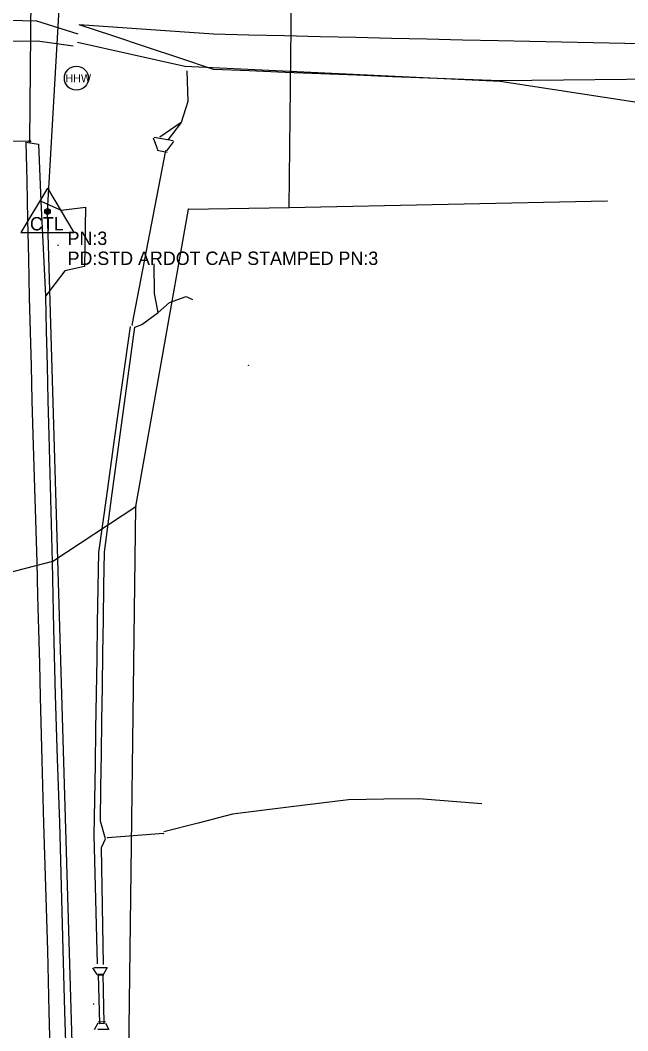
# Model space of a CAD drawing. Extents: x 1930288 to 1941089, y 588389 to 611475.
# Drawn here: x 1930884 to 1931111.5, y 597803.8 to 598182.1 of the extents above; entities that cross this region are included whole.
import ezdxf

# ---------------------------------------------------------------- set-up
doc = ezdxf.new("R2010")
doc.units = 0
for name, color, linetype in [('S_BASELINE', 7, 'Continuous'), ('S_BRIDGE', 7, 'Continuous'), ('S_CROSS_DRAIN', 7, 'Continuous'), ('S_DITCHLINE', 7, 'Continuous'), ('S_DRG_PT_SYM', 7, 'Continuous'), ('S_DRIVEWAY', 7, 'Continuous'), ('S_EDGE_CONCRETE', 7, 'Continuous'), ('S_EDGE_PAVEMENT', 7, 'Continuous'), ('S_HEADWALL', 7, 'Continuous'), ('S_HIST_HIGH_WATER', 7, 'Continuous'), ('S_MSC_PT_SYM', 7, 'Continuous'), ('S_PRIMARY_CTL', 7, 'Continuous'), ('S_PRIMARY_CTL_ANNOT', 7, 'Continuous'), ('S_SANITARY_SEWER', 7, 'Continuous'), ('S_SHOULDER', 7, 'Continuous'), ('S_SIDE_DRAIN', 7, 'Continuous'), ('S_STR_PT_SYM', 7, 'Continuous'), ('S_STREAM', 7, 'Continuous'), ('S_UTL_PT_SYM', 7, 'Continuous'), ('S_WALL', 7, 'Continuous')]:
    doc.layers.add(name, color=color, linetype=linetype)

msp = doc.modelspace()

# ---------------------------------------------------------------- linework, layer by layer
at = {"layer": 'S_BASELINE'}
for p, q in [((1930894.27, 598110.49), (1930946.09, 599020.44)), ((1930922.05, 597172.86), (1930894.27, 598110.49))]:
    msp.add_line(p, q, dxfattribs=at)
at = {"layer": 'S_BRIDGE'}
for p, q in [((1930887.7, 598136.81), (1930888.36, 598226.99)), ((1930860.05, 598137.01), (1930887.7, 598136.81))]:
    msp.add_line(p, q, dxfattribs=at)
at = {"layer": 'S_CROSS_DRAIN'}
for p, q in [((1930915.08, 597824.99), (1930913.16, 597824.9)), ((1930913.16, 597824.9), (1930913.69, 597806.45)), ((1930915.48, 597806.65), (1930915.08, 597824.99)), ((1930913.69, 597806.45), (1930915.48, 597806.65))]:
    msp.add_line(p, q, dxfattribs=at)
at = {"layer": 'S_DITCHLINE'}
for points in [[(1930905.69, 598176.9), (1930890.32, 598181.8), (1930873.87, 598182.1), (1930857.41, 598182.4)], [(1931134.66, 598160.16), (1931111.01, 598159.9), (1931087.35, 598159.64), (1931063.69, 598159.38), (1931050.28, 598159.92), (1931036.87, 598160.45), (1931023.45, 598160.98), (1931010.04, 598161.52), (1930996.63, 598162.05), (1930983.21, 598162.58), (1930969.8, 598163.12), (1930956.39, 598163.65), (1930943.82, 598167.85), (1930931.26, 598172.05), (1930918.7, 598176.25), (1930906.14, 598180.45)], [(1931134.09, 598172.94), (1931110.37, 598173.41), (1931086.65, 598173.88), (1931062.93, 598174.35), (1931049.6, 598174.67), (1931036.28, 598174.99), (1931022.96, 598175.31), (1931009.63, 598175.63), (1930996.31, 598175.95), (1930982.98, 598176.27), (1930969.66, 598176.58), (1930956.34, 598176.9), (1930943.79, 598177.79), (1930931.24, 598178.67), (1930918.69, 598179.56), (1930906.14, 598180.45)], [(1930946.46, 598163.13), (1930946.75, 598151.72), (1930944.27, 598143.85), (1930936.29, 598138.31)], [(1930944.27, 598143.85), (1930939.45, 598137.46)], [(1930915.22, 597828.56), (1930914.87, 597850.48), (1930914.51, 597872.4), (1930915.91, 597875.69), (1930914.06, 597882.24), (1930914.25, 597894.82), (1930914.43, 597907.41), (1930914.62, 597919.99), (1930914.8, 597932.58), (1930914.99, 597945.17), (1930915.18, 597957.75), (1930915.36, 597970.34), (1930915.55, 597982.92), (1930918.38, 598003.99), (1930921.22, 598025.05), (1930924.05, 598046.11), (1930926.89, 598067.17), (1930929.51, 598068.22), (1930935.64, 598072.72), (1930934.26, 598079.76), (1930934.12, 598090.96)], [(1930935.64, 598072.72), (1930939.88, 598076.44), (1930946.19, 598078.67), (1930948.52, 598077.53)], [(1930913.02, 597828.8), (1930912.39, 597852.92), (1930911.76, 597877.04), (1930911.97, 597890.26), (1930912.18, 597903.49), (1930912.39, 597916.71), (1930912.6, 597929.94), (1930912.82, 597943.16), (1930913.03, 597956.39), (1930913.24, 597969.61), (1930913.45, 597982.84), (1930916.41, 598004), (1930919.38, 598025.16), (1930922.34, 598046.32), (1930925.31, 598067.48)], [(1931056.88, 597888.8), (1931033.31, 597890.66), (1931020.1, 597890.46), (1931006.89, 597890.27), (1930985.47, 597887.61), (1930963.53, 597884.9), (1930950.67, 597881.55), (1930937.8, 597878.2)]]:
    msp.add_lwpolyline(points, dxfattribs=at)
at = {"layer": 'S_DRG_PT_SYM'}
for points in [[(1930938.59, 598133.29), (1930938.59, 598133.34), (1930938.59, 598133.29), (1930938.54, 598133.29), (1930938.59, 598133.29), (1930938.59, 598133.24), (1930938.59, 598133.29), (1930938.64, 598133.29)], [(1930925.96, 598067.95), (1930925.96, 598068), (1930925.96, 598067.95), (1930925.91, 598067.95), (1930925.96, 598067.95), (1930925.96, 598067.9), (1930925.96, 598067.95), (1930926.01, 598067.95)], [(1930916.75, 597876.04), (1930916.75, 597876.09), (1930916.75, 597876.04), (1930916.7, 597876.04), (1930916.75, 597876.04), (1930916.75, 597875.99), (1930916.75, 597876.04), (1930916.8, 597876.04)], [(1930937.73, 597877.68), (1930937.73, 597877.73), (1930937.73, 597877.68), (1930937.68, 597877.68), (1930937.73, 597877.68), (1930937.73, 597877.63), (1930937.73, 597877.68), (1930937.78, 597877.68)], [(1930913.16, 597824.9), (1930913.16, 597824.95), (1930913.16, 597824.9), (1930913.11, 597824.9), (1930913.16, 597824.9), (1930913.16, 597824.85), (1930913.16, 597824.9), (1930913.21, 597824.9)], [(1930915.08, 597824.99), (1930915.08, 597825.04), (1930915.08, 597824.99), (1930915.03, 597824.99), (1930915.08, 597824.99), (1930915.08, 597824.94), (1930915.08, 597824.99), (1930915.13, 597824.99)], [(1930913.69, 597806.45), (1930913.69, 597806.5), (1930913.69, 597806.45), (1930913.64, 597806.45), (1930913.69, 597806.45), (1930913.69, 597806.4), (1930913.69, 597806.45), (1930913.74, 597806.45)], [(1930915.48, 597806.65), (1930915.48, 597806.7), (1930915.48, 597806.65), (1930915.43, 597806.65), (1930915.48, 597806.65), (1930915.48, 597806.6), (1930915.48, 597806.65), (1930915.53, 597806.65)]]:
    msp.add_lwpolyline(points, dxfattribs=at)
at = {"layer": 'S_DRIVEWAY'}
msp.add_lwpolyline([(1930891.77, 598114.39), (1930899.31, 598110.95), (1930908.51, 598112.07), (1930908.08, 598089.95), (1930900.79, 598088.32), (1930893.51, 598078.86)], dxfattribs=at)
at = {"layer": 'S_EDGE_CONCRETE'}
for points in [[(1930941.29, 598136.92), (1930934.21, 598138.16)], [(1930911.68, 597827.45), (1930916.28, 597827.51)], [(1930916.82, 597804.31), (1930913.05, 597804.29)]]:
    msp.add_lwpolyline(points, dxfattribs=at)
at = {"layer": 'S_EDGE_PAVEMENT'}
msp.add_lwpolyline([(1930886.18, 598136.44), (1930886.5, 598121.9), (1930886.81, 598107.36), (1930887.13, 598092.81), (1930887.44, 598078.27), (1930887.78, 598065.43), (1930888.11, 598052.59), (1930888.44, 598039.75), (1930888.78, 598026.91), (1930889.5, 598003.04), (1930890.23, 597979.17), (1930890.56, 597966.56), (1930890.9, 597953.94), (1930891.23, 597941.32), (1930891.57, 597928.7), (1930892.18, 597905.05), (1930892.79, 597881.4), (1930893.5, 597857.62), (1930894.2, 597833.84), (1930894.81, 597810.89), (1930895.42, 597787.94)], dxfattribs=at)
at = {"layer": 'S_HEADWALL'}
for points in [[(1930935.25, 598133.48), (1930939.05, 598132.75)], [(1930915.38, 597824.59), (1930913, 597824.51)], [(1930913.17, 597807.18), (1930916, 597807.26)]]:
    msp.add_lwpolyline(points, dxfattribs=at)
at = {"layer": 'S_HIST_HIGH_WATER'}
msp.add_circle((1930905.06, 598160.41), 4.5, dxfattribs=at)
at = {"layer": 'S_MSC_PT_SYM'}
for points in [[(1930898.23, 598097.85), (1930898.23, 598097.9), (1930898.23, 598097.85), (1930898.18, 598097.85), (1930898.23, 598097.85), (1930898.23, 598097.8), (1930898.23, 598097.85), (1930898.28, 598097.85)], [(1930969.55, 598052.91), (1930969.55, 598052.96), (1930969.55, 598052.91), (1930969.5, 598052.91), (1930969.55, 598052.91), (1930969.55, 598052.86), (1930969.55, 598052.91), (1930969.6, 598052.91)], [(1930911.56, 597813.77), (1930911.56, 597813.82), (1930911.56, 597813.77), (1930911.51, 597813.77), (1930911.56, 597813.77), (1930911.56, 597813.72), (1930911.56, 597813.77), (1930911.61, 597813.77)]]:
    msp.add_lwpolyline(points, dxfattribs=at)
at = {"layer": 'S_PRIMARY_CTL'}
for p, q in [((1930894.27, 598119.19), (1930884.23, 598102.68)), ((1930894.27, 598119.19), (1930904.09, 598102.68)), ((1930884.23, 598102.68), (1930904.09, 598102.68))]:
    msp.add_line(p, q, dxfattribs=at)
for radius in [1.04, 0.609, 0.344]:
    msp.add_circle((1930894.27, 598110.49), radius, dxfattribs=at)
at = {"layer": 'S_SANITARY_SEWER'}
for p, q in [((1930984.75, 598112), (1930985.88, 598222.31)), ((1930984.75, 598112), (1931103.79, 598114.5)), ((1930927.31, 598000.04), (1930946.98, 598111.43)), ((1930946.98, 598111.43), (1930984.75, 598112)), ((1930896.27, 597979.53), (1930927.31, 598000.04)), ((1930923.55, 597706.51), (1930927.31, 598000.04)), ((1930837.54, 597964.65), (1930896.27, 597979.53))]:
    msp.add_line(p, q, dxfattribs=at)
at = {"layer": 'S_SHOULDER'}
msp.add_lwpolyline([(1930886.18, 598136.44), (1930890.92, 598135.72), (1930891.77, 598114.39), (1930892.64, 598096.62), (1930893.51, 598078.86), (1930893.81, 598065.81), (1930894.12, 598052.77), (1930894.43, 598039.73), (1930894.73, 598026.69), (1930895.36, 598002.96), (1930895.98, 597979.24), (1930896.54, 597954.32), (1930897.11, 597929.39), (1930897.92, 597905.55), (1930898.74, 597881.7), (1930899.35, 597857.88), (1930899.96, 597834.06), (1930900.65, 597810.97), (1930901.33, 597787.88)], dxfattribs=at)
at = {"layer": 'S_SIDE_DRAIN'}
for p, q in [((1930925.96, 598067.95), (1930938.59, 598133.29)), ((1930937.73, 597877.68), (1930916.75, 597876.04))]:
    msp.add_line(p, q, dxfattribs=at)
at = {"layer": 'S_STR_PT_SYM'}
msp.add_lwpolyline([(1930887.7, 598136.81), (1930887.7, 598137.31), (1930887.7, 598136.81), (1930887.2, 598136.81), (1930887.7, 598136.81), (1930887.7, 598136.31), (1930887.7, 598136.81), (1930888.2, 598136.81)], dxfattribs=at)
at = {"layer": 'S_STREAM'}
for points in [[(1930903.84, 598172.42), (1930890.52, 598174.33), (1930874.09, 598174.21), (1930857.65, 598174.09), (1930841.52, 598174.78), (1930825.38, 598175.47), (1930810.24, 598178.46), (1930795.11, 598181.46), (1930779.97, 598184.46)], [(1931454.95, 598149.53), (1931355.72, 598149.5), (1931273.21, 598145.7), (1931162.17, 598144.02), (1931063.69, 598159.12), (1930945.68, 598164.75), (1930905.43, 598173.73)]]:
    msp.add_lwpolyline(points, dxfattribs=at)
at = {"layer": 'S_UTL_PT_SYM'}
for points in [[(1931103.79, 598114.5), (1931103.79, 598114.55), (1931103.79, 598114.5), (1931103.74, 598114.5), (1931103.79, 598114.5), (1931103.79, 598114.45), (1931103.79, 598114.5), (1931103.84, 598114.5)], [(1930946.98, 598111.43), (1930946.98, 598111.48), (1930946.98, 598111.43), (1930946.93, 598111.43), (1930946.98, 598111.43), (1930946.98, 598111.38), (1930946.98, 598111.43), (1930947.03, 598111.43)], [(1930984.75, 598112), (1930984.75, 598112.05), (1930984.75, 598112), (1930984.7, 598112), (1930984.75, 598112), (1930984.75, 598111.95), (1930984.75, 598112), (1930984.8, 598112)], [(1930984.75, 598112), (1930984.75, 598112.05), (1930984.75, 598112), (1930984.7, 598112), (1930984.75, 598112), (1930984.75, 598111.95), (1930984.75, 598112), (1930984.8, 598112)], [(1930927.31, 598000.04), (1930927.31, 598000.09), (1930927.31, 598000.04), (1930927.26, 598000.04), (1930927.31, 598000.04), (1930927.31, 597999.99), (1930927.31, 598000.04), (1930927.36, 598000.04)], [(1930927.31, 598000.04), (1930927.31, 598000.09), (1930927.31, 598000.04), (1930927.26, 598000.04), (1930927.31, 598000.04), (1930927.31, 597999.99), (1930927.31, 598000.04), (1930927.36, 598000.04)], [(1930896.27, 597979.53), (1930896.27, 597979.58), (1930896.27, 597979.53), (1930896.22, 597979.53), (1930896.27, 597979.53), (1930896.27, 597979.48), (1930896.27, 597979.53), (1930896.32, 597979.53)]]:
    msp.add_lwpolyline(points, dxfattribs=at)
at = {"layer": 'S_WALL'}
for points in [[(1930933.8, 598138.05), (1930935.48, 598133.74)], [(1930938.95, 598133.23), (1930941.5, 598136.69)], [(1930912.81, 597824.82), (1930911.25, 597827.32)], [(1930916.65, 597827.42), (1930915.24, 597824.95)], [(1930911.89, 597804.29), (1930913.24, 597806.71)], [(1930916, 597806.67), (1930917.24, 597804.23)]]:
    msp.add_lwpolyline(points, dxfattribs=at)

# ---------------------------------------------------------------- texts
at = {"layer": 'S_HIST_HIGH_WATER'}
msp.add_text('HHW', height=3, rotation=360, dxfattribs=at).set_placement((1930900.98, 598158.91))
at = {"layer": 'S_PRIMARY_CTL'}
msp.add_text('CTL', height=5, rotation=360, dxfattribs=at).set_placement((1930887.68, 598103.42))
at = {"layer": 'S_PRIMARY_CTL_ANNOT'}
for s, p in [('PN:3', (1930901.77, 598097.99)), ('PD:STD ARDOT CAP STAMPED PN:3', (1930901.77, 598090.49))]:
    msp.add_text(s, height=5, dxfattribs=at).set_placement(p)

doc.saveas('drawing.dxf')
